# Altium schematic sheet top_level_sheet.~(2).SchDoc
size A4
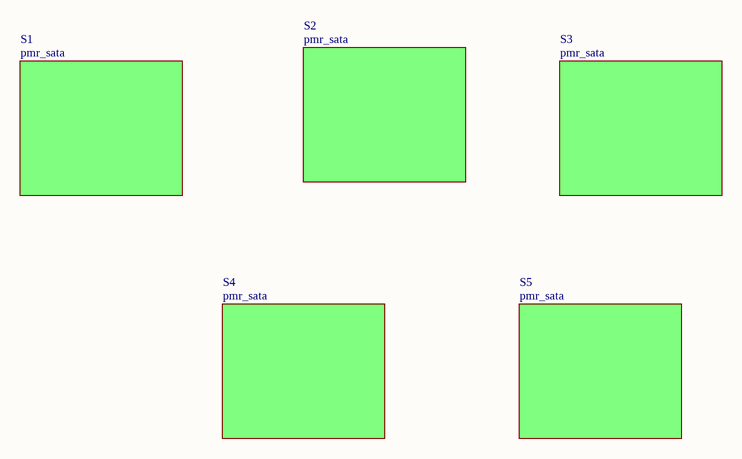
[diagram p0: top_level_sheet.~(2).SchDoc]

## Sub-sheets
S1 = pmr_sata: no entries
S2 = pmr_sata: no entries
S3 = pmr_sata: no entries
S4 = pmr_sata: no entries
S5 = pmr_sata: no entries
